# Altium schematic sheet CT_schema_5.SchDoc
size 368 x 245 mm
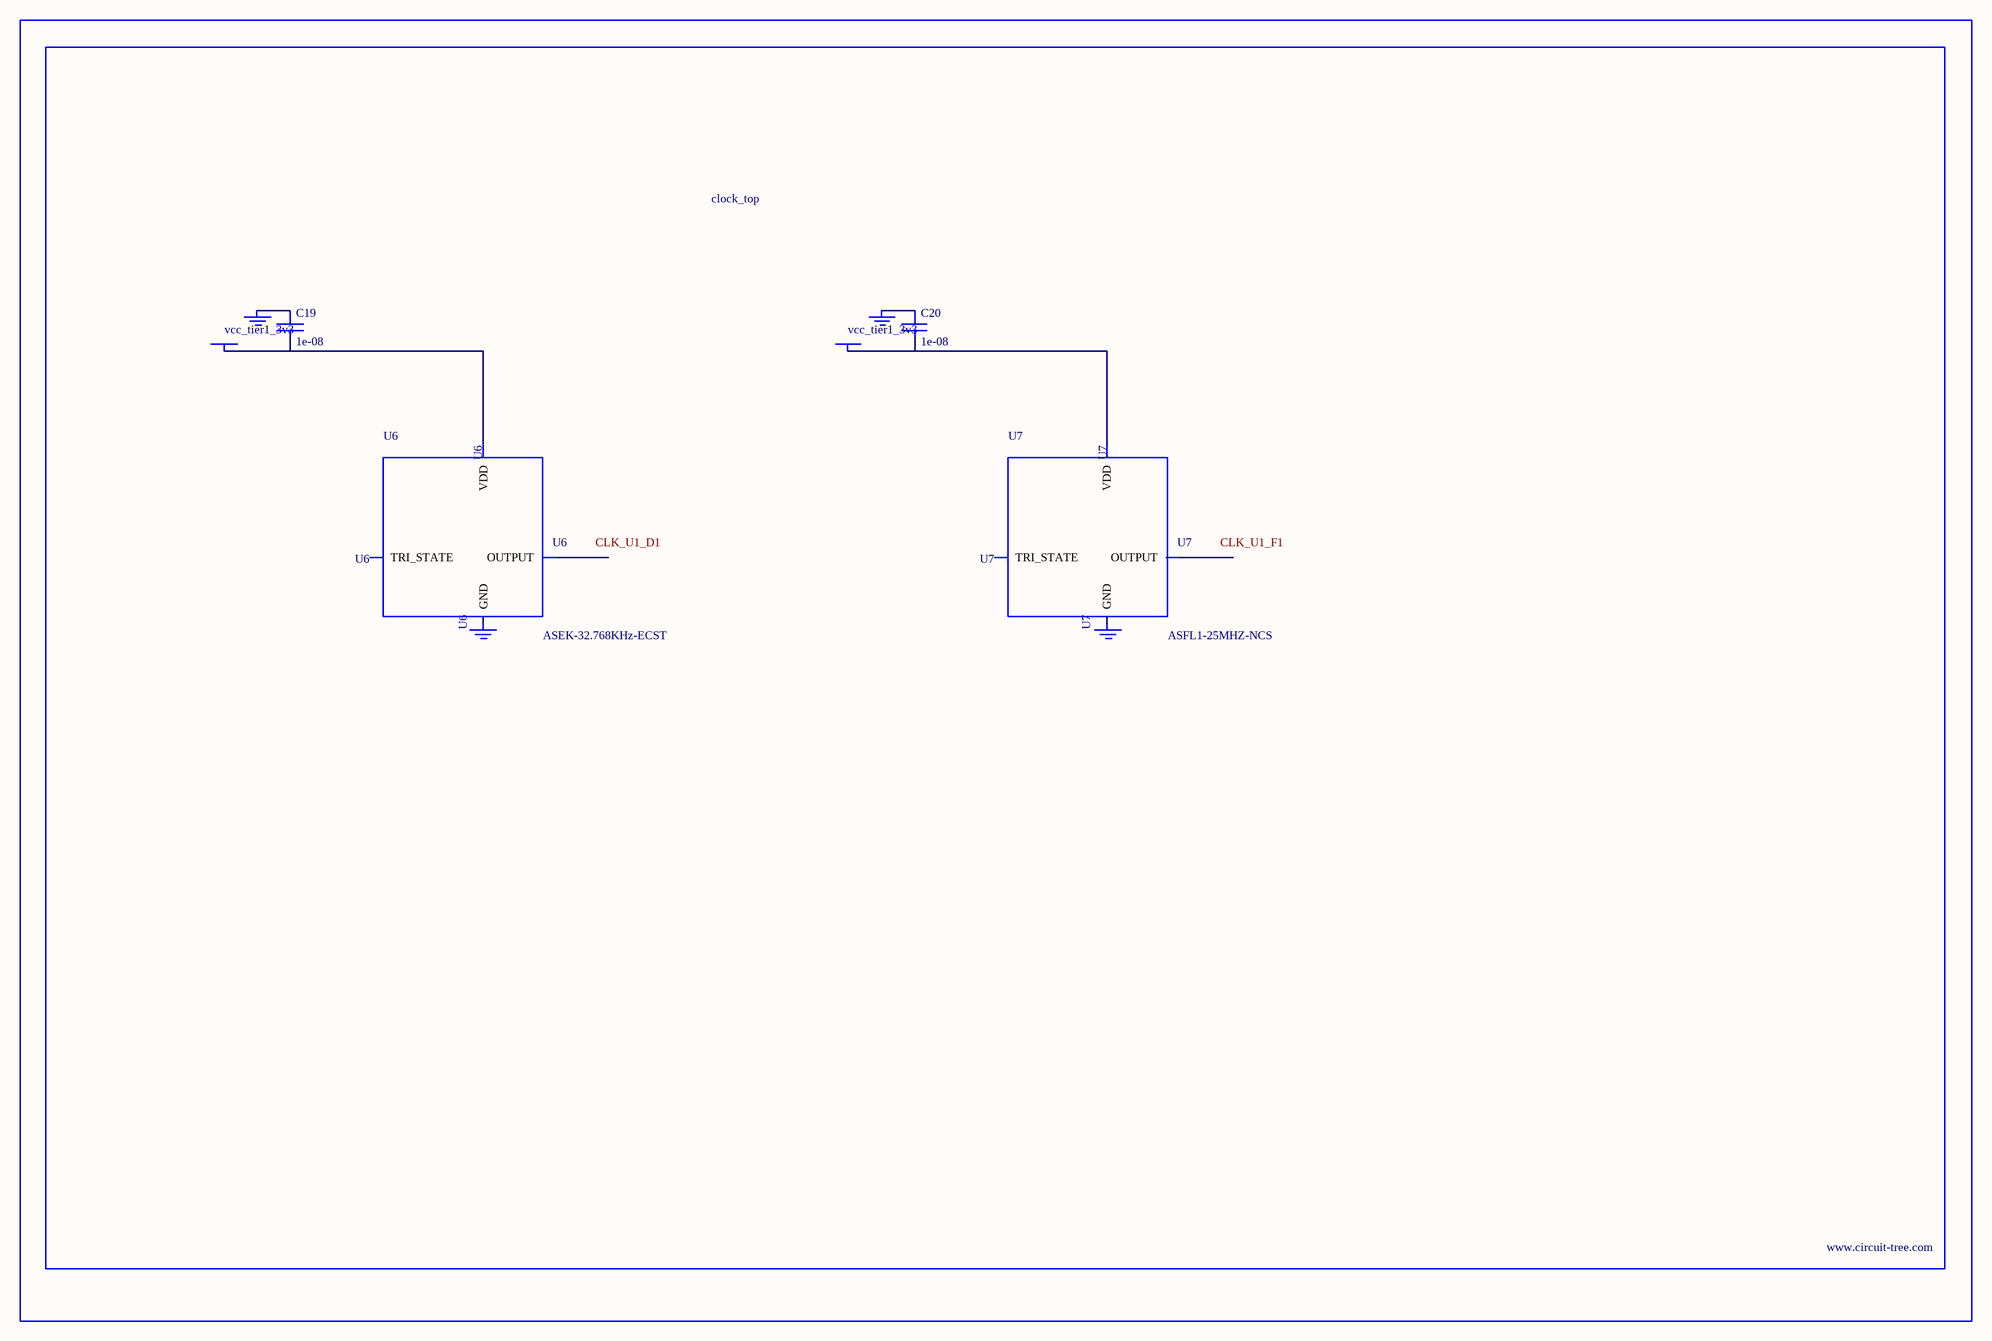
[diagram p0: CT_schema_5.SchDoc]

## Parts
BORDER4  (no value)
C19  1e-08  [C0402]
C20  1e-08  [C0402]
GND_INSTANCE_4_0  (no value)
GND_INSTANCE_4_1  (no value)
GND_INSTANCE_4_2  (no value)
GND_INSTANCE_4_3  (no value)
POWER_INSTANCE_4_0  vcc_tier1_3v3
POWER_INSTANCE_4_1  vcc_tier1_3v3
U6  ASEK-32.768KHz-ECST  [ASEK]
U7  ASFL1-25MHZ-NCS  [ASFL1]

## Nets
NetC19_1: C19.1 GND_INSTANCE_4_0.0(GND)
NetC19_2: C19.2 POWER_INSTANCE_4_0.0(PWR) U6.4(VDD)
NetC20_1: C20.1 GND_INSTANCE_4_2.0(GND)
NetC20_2: C20.2 POWER_INSTANCE_4_1.0(PWR) U7.4(VDD)

Not connected (* = marked no-connect by the designer): GND_INSTANCE_4_1 0(GND); GND_INSTANCE_4_3 0(GND); U6 1(TRI_STATE) 2(GND) 3(OUTPUT); U7 1(TRI_STATE) 2(GND) 3(OUTPUT)

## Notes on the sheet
- Labels drawn without touching a wire or pin: CLK_U1_D1, CLK_U1_F1

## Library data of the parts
BORDER4 = BORDER_PAGE4
C19 C20 = C0402C103K3RAC
GND_INSTANCE_4_0-GND_INSTANCE_4_3 = GND
POWER_INSTANCE_4_0 POWER_INSTANCE_4_1 = PWR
